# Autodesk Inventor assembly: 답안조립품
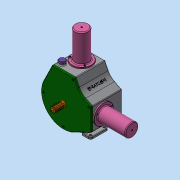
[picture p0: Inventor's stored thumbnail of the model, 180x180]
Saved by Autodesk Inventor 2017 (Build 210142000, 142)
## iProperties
Part Number: 답안조립품
Material: 일반
Document SubType Name: Assembly
Designer: MRC
Mass: 2899.53 g
Surface Area: 4101.78 cm^2
Volume: 1119.43 cm^3
Density: 2.59018 g/cm^3
Author: MRC
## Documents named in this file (13)
- C:\Users\MRC\Desktop\611109V1002\답안조립품.iam
- C:\Users\MRC\Desktop\611109V1002\본체.ipt
- C:\Users\MRC\Desktop\611109V1002\너트 M3.ipt
- C:\Users\MRC\Desktop\611109V1002\베어링 20 x 37 x 9.ipt
- C:\Users\MRC\Desktop\611109V1002\볼트 M3 x 12.ipt
- C:\Users\MRC\Desktop\611109V1002\실린더.ipt
- C:\Users\MRC\Desktop\611109V1002\앞커버.ipt
- C:\Users\MRC\Desktop\611109V1002\축.ipt
- C:\Users\MRC\Desktop\611109V1002\측정게이지.ipt
- C:\Users\MRC\Desktop\611109V1002\커넥팅로드 캡.ipt
- C:\Users\MRC\Desktop\611109V1002\커넥팅로드.ipt
- C:\Users\MRC\Desktop\611109V1002\피스톤 핀.ipt
- C:\Users\MRC\Desktop\611109V1002\피스톤.ipt
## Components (4 placed, 2 different names)
1. 피스톤 핀:1
2. 피스톤:1
3. 피스톤:2
4. 피스톤 핀:2
